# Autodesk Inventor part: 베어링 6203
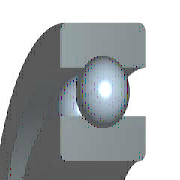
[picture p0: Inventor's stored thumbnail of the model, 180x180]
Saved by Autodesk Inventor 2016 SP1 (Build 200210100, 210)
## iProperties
IsCustomPart: 0
Created: 2016-04
Part Number: 베어링 6203
Material: 강철, 연강
Description: 깊은 그루브 볼 베어링
Document SubType Name: Modeling
Standard: KS B 2023
Designer: mdu
Standards Organization: KS
Language: ko-KR
Size Designation: 6203 - 17 x 40 x 12
Categories: <MemberInstance><Categories><Category DisplayName="샤프트 부품" InternalName="7f7aeb1f-a693-4053-b835-cee3144e0d98" Mnemonic="SHFT"><Category DisplayName="베어링" Inter
Density: 7.86 g/cm^3
Mass: 64.9809 g
Surface Area: 64.3582 cm^2
Volume: 8.26729 cm^3
Appearance: 노란색
Author: mdu
Revision Number: 1
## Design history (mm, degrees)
sketch "스케치" dims "d0" = 5.98 (= -0.26 x WD + 0.26 x BD)
  geometry: L1 (3.01, 14.25)-(8.99, 14.25); L2 (6, 14.25)-(6, 11.26); L3 (6, 14.25)-(6, 17.24); L4 (3.778, 12.249)-(0, 12.249); L5 (0, 8.5)-(12, 8.5); L6 (3.778, 16.251)-(0, 16.251); L7 (0, 20)-(12, 20); L8 (12, 8.5)-(12, 12.249); L9 (8.222, 12.249)-(12, 12.249); L10 (8.222, 16.251)-(12, 16.251); L11 (12, 20)-(12, 16.251); L12 (-1.4, 0)-(8.4, 0) reference; L13 (0, -0.3)-(0, 5.3) reference
  constraints: 22 end point, 4 point on line, 2 collinear, 2 perpendicular, 2 symmetric about line, 1 midpoint, 1 parallel, 14 other
  dimensions: "d9" = 17 diameter of L5 L12 (= WD); "d11" = 40 diameter of L7 L12 (= BD); "d12" = 12 distance between parallel lines of L8 L13 (= KB); "d13" = 24.498 diameter of L9 L12 (= 0.326 x BD + 0.674 x WD)
revolve "본체" stored, may be unused: angle "d6" = 90 deg
revolve "볼" stored, may be unused: angle "d7" = 90 deg
pattern_circular "IDS_ARRAYBALL[SIMPL:T]" dims angle "d3" = 360 deg
body "Solid1"
fillet "모깎기1" dims "d1" = 0.6 (= KRS)
other parameters: "WD" = 17 [user parameter; used in 5 equation terms], "BD" = 40 [user parameter; used in 5 equation terms], "KB" = 12 [user parameter; used in 1 equation term], "KRS" = 0.6 [user parameter; used in 1 equation term], "d4" = 0, "d5" = 0, "d8" = 0, "d14" = 0, "d15" = 0, "BBA" = 0 [user parameter], "BC0" = 4750000 [user parameter], "BC" = 9560000 [user parameter], "WR" = 8.5 (= 0.5 x WD) [user parameter]
